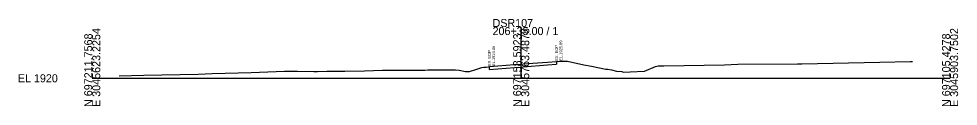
# Model space of a CAD drawing. Extents: x -26 to 19003, y -31 to 24541.
# Drawn here: x 1974.3 to 2302.8, y 10990.3 to 11020.7 of the extents above; entities that cross this region are included whole.
import ezdxf

# ---------------------------------------------------------------- set-up
doc = ezdxf.new("R2010")
doc.units = 0
for name, color, linetype in [('DESIGN - SHEET - Light Grid', 7, 'Continuous'), ('SURVEY - GROUND - Existing Pavement Layer', 7, 'Continuous'), ('SURVEY - GROUND - Existing Pavement Text', 7, 'Continuous'), ('SURVEY - GROUND - Top of Ground', 7, 'Continuous')]:
    doc.layers.add(name, color=color, linetype=linetype)

msp = doc.modelspace()

# ---------------------------------------------------------------- linework, layer by layer
at = {"layer": 'DESIGN - SHEET - Light Grid'}
for p, q in [((2150, 11000), (2150, 11017.85)), ((2000, 11000), (2150, 11000)), ((2150, 11000), (2300, 11000))]:
    msp.add_line(p, q, dxfattribs=at)
at = {"layer": 'SURVEY - GROUND - Existing Pavement Layer'}
for p, q in [((2162.36, 11005.89), (2162.36, 11004.89)), ((2138.87, 11003.06), (2138.87, 11004.06)), ((2138.87, 11003.06), (2147.62, 11003.75)), ((2147.62, 11003.75), (2150, 11003.93)), ((2150, 11003.93), (2150.68, 11003.98)), ((2150.68, 11003.98), (2159.17, 11004.64)), ((2159.17, 11004.64), (2162.36, 11004.89))]:
    msp.add_line(p, q, dxfattribs=at)
at = {"layer": 'SURVEY - GROUND - Top of Ground'}
msp.add_lwpolyline([(2009.42, 11000.87), (2018.03, 11001.05), (2037.04, 11001.43), (2041.89, 11001.64), (2055.55, 11002.01), (2067.23, 11002.47), (2071.76, 11002.44), (2077.5, 11002.36), (2078.82, 11002.38), (2082.09, 11002.45), (2088.29, 11002.47), (2095.19, 11002.62), (2101.49, 11002.8), (2116.35, 11002.88), (2117.39, 11002.89), (2127.08, 11002.96), (2128.29, 11002.84), (2130.55, 11002.39), (2131.88, 11002.42), (2132.33, 11002.43), (2133.8, 11002.89), (2136.3, 11003.77), (2136.93, 11003.85), (2137.75, 11003.93), (2138.42, 11004.01), (2138.87, 11004.06), (2147.62, 11004.75), (2150, 11004.93), (2150.68, 11004.98), (2159.17, 11005.64), (2162.36, 11005.89), (2163.51, 11005.95), (2164.2, 11005.93), (2166.21, 11005.91), (2171.92, 11004.69), (2174.64, 11004.19), (2179.63, 11003.23), (2180.35, 11003.2), (2181.62, 11002.98), (2183.37, 11002.51), (2185.25, 11002.31), (2185.65, 11002.16), (2188.08, 11002.24), (2193.08, 11002.44), (2197.03, 11004.1), (2197.89, 11004.34), (2199.87, 11004.31), (2221.1, 11004.74), (2225.77, 11004.86), (2246.59, 11005.02), (2248.18, 11005.07), (2275.42, 11005.61), (2286.03, 11005.81), (2286.84, 11005.83)], dxfattribs=at)

# ---------------------------------------------------------------- texts
at = {"layer": 'DESIGN - SHEET - Light Grid'}
for s, p in [('DSR107', (2140, 11017.85)), ('206+35.00 / 1', (2140, 11015.05)), ('EL 1920', (1974, 10998.6))]:
    msp.add_text(s, height=2.8, dxfattribs=at).set_placement(p)
for s, p in [('E 3045623.2254', (2002.8, 10990)), ('E 3045763.4878', (2152.8, 10990)), ('E 3045903.7502', (2302.8, 10990)), ('N 697211.7568', (2000, 10990)), ('N 697158.5923', (2150, 10990)), ('N 697105.4278', (2300, 10990))]:
    msp.add_text(s, height=2.8, rotation=90, dxfattribs=at).set_placement(p)
at = {"layer": 'SURVEY - GROUND - Existing Pavement Text'}
for s, p in [('EL.1925.89', (2164.36, 11006.09)), ('EX. EOP', (2139.37, 11004.26)), ('EL.1924.06', (2140.87, 11004.26)), ('EX. EOP', (2162.86, 11006.09))]:
    msp.add_text(s, height=1, rotation=90, dxfattribs=at).set_placement(p)

doc.saveas('drawing.dxf')
